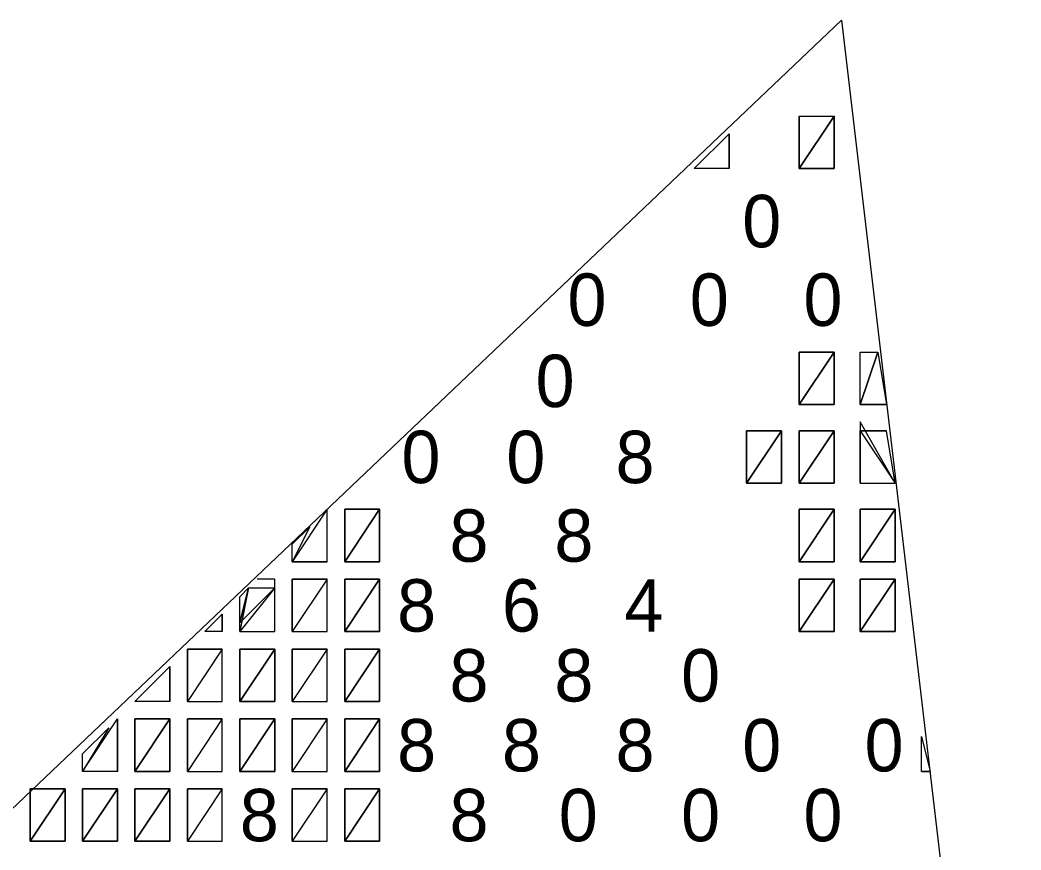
# Model space of a CAD drawing. Extents: x 0 to 34, y -1.2 to 22.
# Drawn here: x 3.4427 to 3.7687, y 4.6293 to 4.8996 of the extents above; entities that cross this region are included whole.
import ezdxf

# ---------------------------------------------------------------- set-up
doc = ezdxf.new("R2010")
doc.units = 0
doc.layers.add('Default', color=7, linetype='Continuous')

msp = doc.modelspace()

# ---------------------------------------------------------------- linework, layer by layer
at = {"layer": 'Default'}
for p, q in [((3.71021, 4.89963), (3.34713, 4.55419)), ((3.71021, 4.89963), (3.76865, 4.40245)), ((3.6964, 4.86828), (3.6964, 4.85121)), ((3.70778, 4.85121), (3.70778, 4.86828)), ((3.67363, 4.85121), (3.67363, 4.86259)), ((3.67363, 4.85121), (3.66225, 4.85121)), ((3.6964, 4.85121), (3.70778, 4.85121)), ((3.70778, 4.79146), (3.6964, 4.79146)), ((3.6964, 4.79146), (3.6964, 4.77439)), ((3.70778, 4.77439), (3.70778, 4.79146)), ((3.71631, 4.79146), (3.722, 4.79146)), ((3.71631, 4.77439), (3.71631, 4.79146)), ((3.6964, 4.77439), (3.70778, 4.77439)), ((3.71631, 4.77439), (3.72485, 4.77439)), ((3.69071, 4.76586), (3.67932, 4.76586)), ((3.67932, 4.76586), (3.67932, 4.74878)), ((3.69071, 4.74878), (3.69071, 4.76586)), ((3.6964, 4.76586), (3.6964, 4.74878)), ((3.70778, 4.76586), (3.6964, 4.76586)), ((3.70778, 4.74878), (3.70778, 4.76586)), ((3.71631, 4.76586), (3.72485, 4.76586)), ((3.71631, 4.74878), (3.71631, 4.76586)), ((3.67932, 4.74878), (3.69071, 4.74878)), ((3.6964, 4.74878), (3.70778, 4.74878)), ((3.71631, 4.74878), (3.72769, 4.74878)), ((3.54276, 4.72318), (3.54276, 4.74025)), ((3.54845, 4.74025), (3.54845, 4.72318)), ((3.55983, 4.74025), (3.54845, 4.74025)), ((3.55983, 4.72318), (3.55983, 4.74025)), ((3.70778, 4.74025), (3.6964, 4.74025)), ((3.6964, 4.74025), (3.6964, 4.72318)), ((3.70778, 4.72318), (3.70778, 4.74025)), ((3.72769, 4.74025), (3.71631, 4.74025)), ((3.71631, 4.74025), (3.71631, 4.72318)), ((3.72769, 4.72318), (3.72769, 4.74025)), ((3.53137, 4.72318), (3.53137, 4.72887)), ((3.54276, 4.72318), (3.53137, 4.72318)), ((3.54845, 4.72318), (3.55983, 4.72318)), ((3.6964, 4.72318), (3.70778, 4.72318)), ((3.71631, 4.72318), (3.72769, 4.72318)), ((3.52568, 4.71749), (3.51999, 4.71749)), ((3.52568, 4.70042), (3.52568, 4.71749)), ((3.54276, 4.71749), (3.53137, 4.71749)), ((3.53137, 4.71749), (3.53137, 4.70042)), ((3.54276, 4.70042), (3.54276, 4.71749)), ((3.55983, 4.71749), (3.54845, 4.71749)), ((3.54845, 4.71749), (3.54845, 4.70042)), ((3.55983, 4.70042), (3.55983, 4.71749)), ((3.6964, 4.71749), (3.6964, 4.70042)), ((3.70778, 4.71749), (3.6964, 4.71749)), ((3.70778, 4.70042), (3.70778, 4.71749)), ((3.71631, 4.71749), (3.71631, 4.70042)), ((3.72769, 4.71749), (3.71631, 4.71749)), ((3.72769, 4.70042), (3.72769, 4.71749)), ((3.5143, 4.70042), (3.5143, 4.7118)), ((3.50861, 4.70042), (3.50861, 4.70611)), ((3.50861, 4.70042), (3.50292, 4.70042)), ((3.5143, 4.70042), (3.52568, 4.70042)), ((3.53137, 4.70042), (3.54276, 4.70042)), ((3.54845, 4.70042), (3.55983, 4.70042)), ((3.6964, 4.70042), (3.70778, 4.70042)), ((3.71631, 4.70042), (3.72769, 4.70042)), ((3.50861, 4.69473), (3.49723, 4.69473)), ((3.49723, 4.69473), (3.49723, 4.67765)), ((3.50861, 4.67765), (3.50861, 4.69473)), ((3.5143, 4.69473), (3.5143, 4.67765)), ((3.52568, 4.69473), (3.5143, 4.69473)), ((3.52568, 4.67765), (3.52568, 4.69473)), ((3.54276, 4.69473), (3.53137, 4.69473)), ((3.53137, 4.69473), (3.53137, 4.67765)), ((3.54276, 4.67765), (3.54276, 4.69473)), ((3.55983, 4.69473), (3.54845, 4.69473)), ((3.54845, 4.69473), (3.54845, 4.67765)), ((3.55983, 4.67765), (3.55983, 4.69473)), ((3.49154, 4.67765), (3.49154, 4.68904)), ((3.49154, 4.67765), (3.48016, 4.67765)), ((3.49723, 4.67765), (3.50861, 4.67765)), ((3.5143, 4.67765), (3.52568, 4.67765)), ((3.53137, 4.67765), (3.54276, 4.67765)), ((3.54845, 4.67765), (3.55983, 4.67765)), ((3.47447, 4.65489), (3.47447, 4.67196)), ((3.48016, 4.67196), (3.48016, 4.65489)), ((3.49154, 4.67196), (3.48016, 4.67196)), ((3.49154, 4.65489), (3.49154, 4.67196)), ((3.49723, 4.67196), (3.49723, 4.65489)), ((3.50861, 4.67196), (3.49723, 4.67196)), ((3.50861, 4.65489), (3.50861, 4.67196)), ((3.5143, 4.67196), (3.5143, 4.65489)), ((3.52568, 4.67196), (3.5143, 4.67196)), ((3.52568, 4.65489), (3.52568, 4.67196)), ((3.53137, 4.67196), (3.53137, 4.65489)), ((3.54276, 4.67196), (3.53137, 4.67196)), ((3.54276, 4.65489), (3.54276, 4.67196)), ((3.54845, 4.67196), (3.54845, 4.65489)), ((3.55983, 4.67196), (3.54845, 4.67196)), ((3.55983, 4.65489), (3.55983, 4.67196)), ((3.73623, 4.65489), (3.73623, 4.66627)), ((3.47447, 4.65489), (3.46309, 4.65489)), ((3.48016, 4.65489), (3.49154, 4.65489)), ((3.49723, 4.65489), (3.50861, 4.65489)), ((3.5143, 4.65489), (3.52568, 4.65489)), ((3.53137, 4.65489), (3.54276, 4.65489)), ((3.54845, 4.65489), (3.55983, 4.65489)), ((3.73623, 4.65489), (3.73907, 4.65489)), ((3.44602, 4.6492), (3.44602, 4.63213)), ((3.4574, 4.6492), (3.44602, 4.6492)), ((3.4574, 4.63213), (3.4574, 4.6492)), ((3.47447, 4.6492), (3.46309, 4.6492)), ((3.46309, 4.6492), (3.46309, 4.63213)), ((3.47447, 4.63213), (3.47447, 4.6492)), ((3.48016, 4.6492), (3.48016, 4.63213)), ((3.49154, 4.6492), (3.48016, 4.6492)), ((3.49154, 4.63213), (3.49154, 4.6492)), ((3.50861, 4.6492), (3.49723, 4.6492)), ((3.49723, 4.6492), (3.49723, 4.63213)), ((3.50861, 4.63213), (3.50861, 4.6492)), ((3.54276, 4.6492), (3.53137, 4.6492)), ((3.53137, 4.6492), (3.53137, 4.63213)), ((3.54276, 4.63213), (3.54276, 4.6492)), ((3.55983, 4.6492), (3.54845, 4.6492)), ((3.54845, 4.6492), (3.54845, 4.63213)), ((3.55983, 4.63213), (3.55983, 4.6492)), ((3.44602, 4.63213), (3.4574, 4.63213)), ((3.46309, 4.63213), (3.47447, 4.63213)), ((3.48016, 4.63213), (3.49154, 4.63213)), ((3.49723, 4.63213), (3.50861, 4.63213)), ((3.53137, 4.63213), (3.54276, 4.63213)), ((3.54845, 4.63213), (3.55983, 4.63213))]:
    msp.add_line(p, q, dxfattribs=at)
for points in [[(3.70778, 4.86828), (3.70778, 4.85121), (3.6964, 4.85121)], [(3.6964, 4.85121), (3.6964, 4.86828), (3.70778, 4.86828)], [(3.66225, 4.85121), (3.67363, 4.86259), (3.67363, 4.85121)], [(3.6964, 4.77439), (3.6964, 4.79146), (3.70778, 4.79146)], [(3.70778, 4.79146), (3.70778, 4.77439), (3.6964, 4.77439)], [(3.71631, 4.77439), (3.71631, 4.79146), (3.722, 4.79146)], [(3.72485, 4.77439), (3.71631, 4.77439), (3.722, 4.79146)], [(3.71631, 4.7687), (3.71631, 4.74878), (3.72769, 4.74878)], [(3.67932, 4.74878), (3.67932, 4.76586), (3.69071, 4.76586)], [(3.69071, 4.76586), (3.69071, 4.74878), (3.67932, 4.74878)], [(3.70778, 4.76586), (3.70778, 4.74878), (3.6964, 4.74878)], [(3.6964, 4.74878), (3.6964, 4.76586), (3.70778, 4.76586)], [(3.72769, 4.74878), (3.72485, 4.76586), (3.71631, 4.76586)], [(3.53137, 4.72318), (3.54276, 4.72318), (3.54276, 4.74025)], [(3.55983, 4.74025), (3.55983, 4.72318), (3.54845, 4.72318)], [(3.54845, 4.72318), (3.54845, 4.74025), (3.55983, 4.74025)], [(3.6964, 4.72318), (3.6964, 4.74025), (3.70778, 4.74025)], [(3.70778, 4.74025), (3.70778, 4.72318), (3.6964, 4.72318)], [(3.71631, 4.72318), (3.71631, 4.74025), (3.72769, 4.74025)], [(3.72769, 4.74025), (3.72769, 4.72318), (3.71631, 4.72318)], [(3.53137, 4.72318), (3.53137, 4.72887), (3.53707, 4.73456)], [(3.53137, 4.70042), (3.54276, 4.70042), (3.54276, 4.71749)], [(3.53137, 4.70042), (3.53137, 4.71749), (3.54276, 4.71749)], [(3.54845, 4.70042), (3.54845, 4.71749), (3.55983, 4.71749)], [(3.55983, 4.71749), (3.55983, 4.70042), (3.54845, 4.70042)], [(3.70778, 4.71749), (3.70778, 4.70042), (3.6964, 4.70042)], [(3.6964, 4.70042), (3.6964, 4.71749), (3.70778, 4.71749)], [(3.72769, 4.71749), (3.72769, 4.70042), (3.71631, 4.70042)], [(3.71631, 4.70042), (3.71631, 4.71749), (3.72769, 4.71749)], [(3.5143, 4.70326), (3.51715, 4.71464), (3.52568, 4.71464)], [(3.51715, 4.71464), (3.51715, 4.71464), (3.5143, 4.70326)], [(3.5143, 4.70042), (3.5143, 4.7118), (3.51715, 4.71464)], [(3.5143, 4.70042), (3.52568, 4.70042), (3.52568, 4.71464)], [(3.50292, 4.70042), (3.50861, 4.70611), (3.50861, 4.70042)], [(3.49723, 4.67765), (3.50861, 4.67765), (3.50861, 4.69473)], [(3.49723, 4.67765), (3.49723, 4.69473), (3.50861, 4.69473)], [(3.52568, 4.69473), (3.52568, 4.67765), (3.5143, 4.67765)], [(3.5143, 4.67765), (3.5143, 4.69473), (3.52568, 4.69473)], [(3.53137, 4.67765), (3.54276, 4.67765), (3.54276, 4.69473)], [(3.53137, 4.67765), (3.53137, 4.69473), (3.54276, 4.69473)], [(3.54845, 4.67765), (3.54845, 4.69473), (3.55983, 4.69473)], [(3.55983, 4.69473), (3.55983, 4.67765), (3.54845, 4.67765)], [(3.48016, 4.67765), (3.49154, 4.68904), (3.49154, 4.67765)], [(3.46309, 4.65489), (3.47447, 4.67196), (3.47447, 4.65489)], [(3.49154, 4.67196), (3.49154, 4.65489), (3.48016, 4.65489)], [(3.48016, 4.65489), (3.48016, 4.67196), (3.49154, 4.67196)], [(3.49723, 4.65489), (3.50861, 4.65489), (3.50861, 4.67196)], [(3.49723, 4.65489), (3.49723, 4.67196), (3.50861, 4.67196)], [(3.52568, 4.67196), (3.52568, 4.65489), (3.5143, 4.65489)], [(3.5143, 4.65489), (3.5143, 4.67196), (3.52568, 4.67196)], [(3.53137, 4.65489), (3.54276, 4.65489), (3.54276, 4.67196)], [(3.53137, 4.65489), (3.53137, 4.67196), (3.54276, 4.67196)], [(3.54845, 4.65489), (3.54845, 4.67196), (3.55983, 4.67196)], [(3.55983, 4.67196), (3.55983, 4.65489), (3.54845, 4.65489)], [(3.46309, 4.65489), (3.46309, 4.66058), (3.47163, 4.66912)], [(3.73907, 4.65489), (3.73623, 4.65489), (3.73623, 4.66627)], [(3.44602, 4.63213), (3.44602, 4.6492), (3.4574, 4.6492)], [(3.4574, 4.6492), (3.4574, 4.63213), (3.44602, 4.63213)], [(3.4574, 4.6492), (3.4574, 4.6492), (3.4574, 4.6492)], [(3.46309, 4.63213), (3.46309, 4.6492), (3.47447, 4.6492)], [(3.47447, 4.6492), (3.47447, 4.63213), (3.46309, 4.63213)], [(3.49154, 4.6492), (3.49154, 4.63213), (3.48016, 4.63213)], [(3.48016, 4.63213), (3.48016, 4.6492), (3.49154, 4.6492)], [(3.49723, 4.63213), (3.50861, 4.63213), (3.50861, 4.6492)], [(3.49723, 4.63213), (3.49723, 4.6492), (3.50861, 4.6492)], [(3.53137, 4.63213), (3.54276, 4.63213), (3.54276, 4.6492)], [(3.53137, 4.63213), (3.53137, 4.6492), (3.54276, 4.6492)], [(3.54845, 4.63213), (3.54845, 4.6492), (3.55983, 4.6492)], [(3.55983, 4.6492), (3.55983, 4.63213), (3.54845, 4.63213)]]:
    msp.add_lwpolyline(points, close=True, dxfattribs=at)

# ---------------------------------------------------------------- texts
for s, p in [('0', (3.6779, 4.8256)), ('0', (3.621, 4.8)), ('0', (3.66083, 4.8)), ('0', (3.69782, 4.8)), ('0', (3.61062, 4.77355)), ('0', (3.56694, 4.74878)), ('0', (3.60108, 4.74878)), ('8', (3.63665, 4.74878)), ('8', (3.58259, 4.72318)), ('8', (3.61673, 4.72318)), ('8', (3.56552, 4.70042)), ('6', (3.59966, 4.70042)), ('4', (3.63949, 4.70042)), ('8', (3.58259, 4.67765)), ('8', (3.61673, 4.67765)), ('0', (3.65799, 4.67765)), ('8', (3.56552, 4.65489)), ('8', (3.59966, 4.65489)), ('8', (3.63665, 4.65489)), ('0', (3.6779, 4.65489)), ('0', (3.71773, 4.65489)), ('8', (3.5143, 4.63213)), ('8', (3.58259, 4.63213)), ('0', (3.61815, 4.63213)), ('0', (3.65799, 4.63213)), ('0', (3.69782, 4.63213))]:
    msp.add_text(s, height=0.01707, dxfattribs=at).set_placement(p)

doc.saveas('drawing.dxf')
